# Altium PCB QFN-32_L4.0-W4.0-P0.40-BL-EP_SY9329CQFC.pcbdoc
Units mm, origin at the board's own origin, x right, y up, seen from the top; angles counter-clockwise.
Board outline 17.5 x 17.6 mm, 2 copper layers (Top Layer, Bottom Layer), stack 0 mm thick; 1 components, 0 nets, 33 pads, 0 vias.
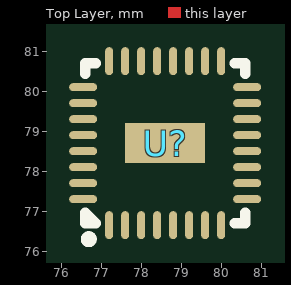
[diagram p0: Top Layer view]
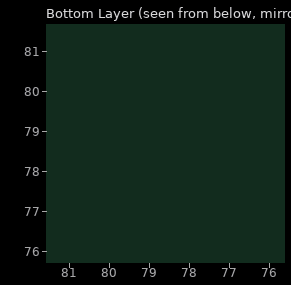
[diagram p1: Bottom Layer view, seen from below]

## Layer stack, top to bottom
Top Layer: signal copper (thickness not stored)
Bottom Layer: signal copper (thickness not stored)

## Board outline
87.35,69.85 69.85,69.85 69.85,87.45 87.35,87.45

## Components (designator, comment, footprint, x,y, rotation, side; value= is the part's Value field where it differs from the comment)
U? "" QFN-32_L4.0-W4.0-P0.40-BL-EP_SY9329CQFC 78.6,78.7 r0 top

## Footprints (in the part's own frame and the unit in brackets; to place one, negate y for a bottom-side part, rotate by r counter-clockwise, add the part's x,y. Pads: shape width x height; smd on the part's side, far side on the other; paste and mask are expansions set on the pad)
QFN-32_L4.0-W4.0-P0.40-BL-EP_SY9329CQFC [mm]
  oval 0.2x0.7 smd: 1(-1.4,-2.05) 2(-1,-2.05) 3(-0.6,-2.05) 4(-0.2,-2.05) 5(0.2,-2.05) 6(0.6,-2.05) 7(1,-2.05) 8(1.4,-2.05) 17(1.4,2.05) 18(1,2.05) 19(0.6,2.05) 20(0.2,2.05) 21(-0.2,2.05) 22(-0.6,2.05) 23(-1,2.05) 24(-1.4,2.05)
  oval 0.7x0.2 smd: 9(2.05,-1.4) 10(2.05,-1) 11(2.05,-0.6) 12(2.05,-0.2) 13(2.05,0.2) 14(2.05,0.6) 15(2.05,1) 16(2.05,1.4) 25(-2.05,1.4) 26(-2.05,1) 27(-2.05,0.6) 28(-2.05,0.2) 29(-2.05,-0.2) 30(-2.05,-0.6) 31(-2.05,-1) 32(-2.05,-1.4)
  rect 2x1 smd: 33(0,0)
  silkscreen extent -2.01,-2.5 2,2

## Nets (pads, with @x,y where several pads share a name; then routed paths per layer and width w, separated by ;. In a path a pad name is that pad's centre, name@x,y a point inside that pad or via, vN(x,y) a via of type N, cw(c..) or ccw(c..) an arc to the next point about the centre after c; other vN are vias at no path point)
pads on no net: U?.1 U?.2 U?.3 U?.4 U?.5 U?.6 U?.7 U?.8 U?.9 U?.10 U?.11 U?.12 U?.13 U?.14 U?.15 U?.16 U?.17 U?.18 U?.19 U?.20 U?.21 U?.22 U?.23 U?.24 U?.25 U?.26 U?.27 U?.28 U?.29 U?.30 U?.31 U?.32 U?.33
